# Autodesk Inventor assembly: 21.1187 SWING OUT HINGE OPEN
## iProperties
Created: 2007-07
Part Number: 21.1187 SWING OUT HINGE OPEN
Document SubType Name: Assembly
Designer: Andy Moles
Author: Andy Moles
